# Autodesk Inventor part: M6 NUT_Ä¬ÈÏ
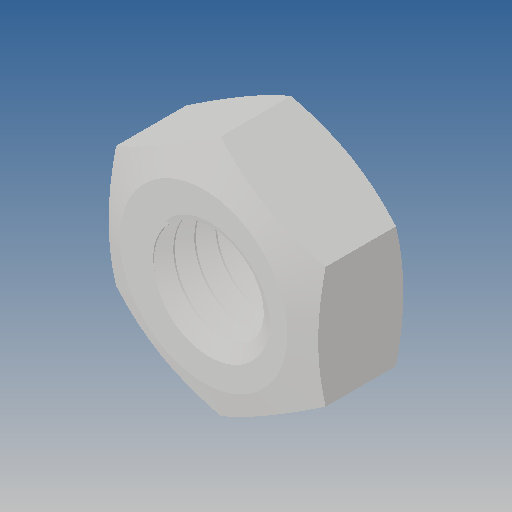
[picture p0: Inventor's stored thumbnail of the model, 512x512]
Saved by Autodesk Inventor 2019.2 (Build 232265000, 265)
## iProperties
Created: 2010-06
Part Number: M6 NUT_Ä¬ÈÏ
Material: Ogólny
Document SubType Name: Modeling
Designer: CADENGINEERING4
Density: 1 g/cm^3
Appearance: Domyślna
Author: CADENGINEERING4
Revision Number: ÈÎºÎ
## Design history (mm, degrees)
feature "NONE"
node "Bryła1"
